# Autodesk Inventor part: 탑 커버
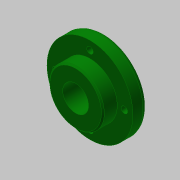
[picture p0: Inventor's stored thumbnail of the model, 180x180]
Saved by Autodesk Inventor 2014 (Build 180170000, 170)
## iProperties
Created: 2016-08
Part Number: 탑 커버
Material: 알루미늄 6061
Document SubType Name: Modeling
Designer: mduedu
Density: 2.71 g/cm^3
Appearance: 진녹색
Author: mduedu
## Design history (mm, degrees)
sketch "스케치1"
  geometry: L1 (0, 0)-(0, 10); L2 (0, 10)-(-30, 10); L3 (-30, 10)-(-30, 0); L4 (-30, 0)-(-19, 0); L5 (-19, 0)-(-19, -10); L6 (-19, -10)-(0, -10); L7 (0, -10)-(0, 10); 2 further points
  constraints: 14 end point, 3 parallel, 3 perpendicular, 1 coincident, 1 horizontal alignment, 1 midpoint, 1 vertical
  dimensions: "d0" = 10 distance of L1.start L1.end; "d2" = 60 diameter of L3 L1; "d3" = 38 diameter of L5 L1; "d4" = 20 distance between parallel lines of L6 L2
revolve "회전1" sketch "스케치1" stored, may be unused: angle "d5" = 90 deg
hole "구멍1" diameter "d8" = 18; stored, may be unused: countersink angle "d12" = 90 deg, drill point angle "d14" = 118 deg; dims "d6" = 10, "d7" = 10, "d9" = 6, "d10" = 4, "d11" = 2, "d13" = 8
chamfer "모따기1" distance "d15" = 1; stored, may be unused: second distance "d16" = 2, angle "d17" = 45 deg
chamfer "모따기2" distance "d18" = 1; stored, may be unused: second distance "d19" = 2, angle "d20" = 45 deg
fillet "모깎기1" dims "d21" = 3
sketch "스케치2" dims "d22" = 48
  geometry: 6 further points
  constraints: 2 vertical alignment, 1 coincident, 7 other
  dimensions: "d26" = 360 deg dimension on point (0, 0) point (0, 24) (derived)
sketch "스케치3"
  geometry: 4 further points
hole "구멍2" sketch "스케치3" at (-24, 0), (0, -24), (24, 0), (0, 24) diameter "d28" = 4.5; stored, may be unused: countersink angle "d32" = 90 deg, drill point angle "d34" = 0 deg; dims "d29" = 6, "d30" = 8, "d31" = 4.6, "d33" = 8
node "솔리드1"
